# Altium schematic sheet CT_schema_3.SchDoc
size 176 x 147 mm
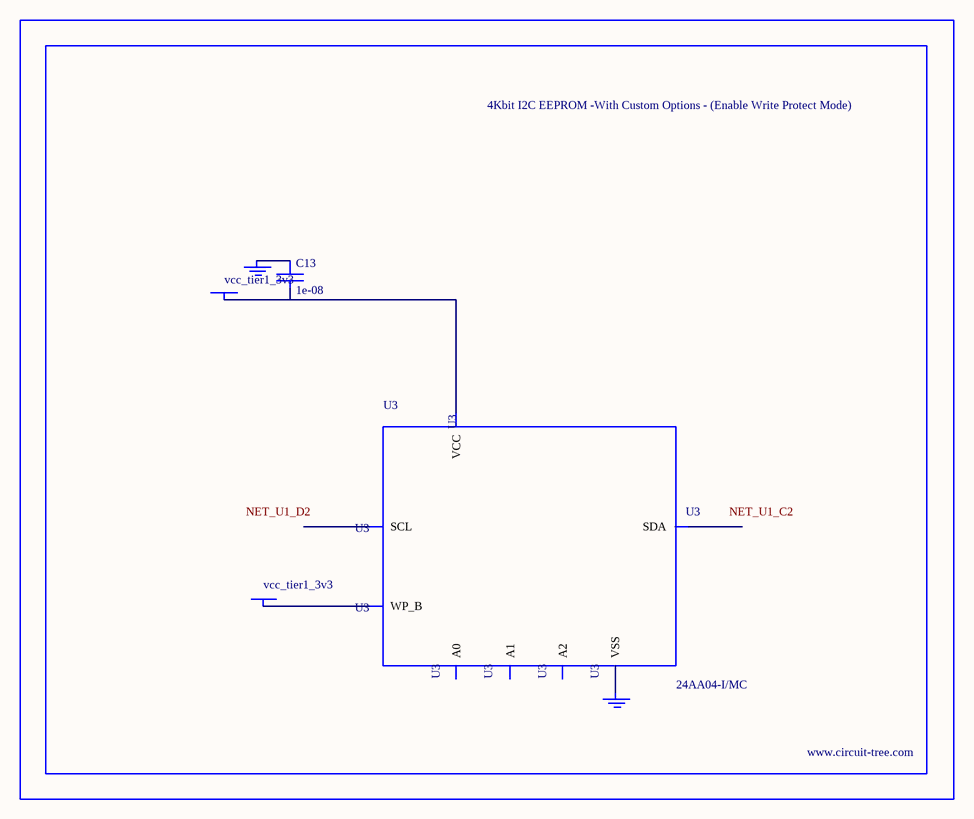
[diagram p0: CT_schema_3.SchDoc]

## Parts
BORDER2  (no value)
C13  1e-08  [C0402]
GND_INSTANCE_2_0  (no value)
GND_INSTANCE_2_1  (no value)
POWER_INSTANCE_2_0  vcc_tier1_3v3
POWER_INSTANCE_2_1  vcc_tier1_3v3
U3  24AA04-I/MC  [TDFN-8/6MM]

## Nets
NetC13_1: C13.1 GND_INSTANCE_2_0.0(GND)
NetC13_2: C13.2 POWER_INSTANCE_2_1.0(PWR) U3.8(VCC)
NetGND_INSTANCE_2_1_0: GND_INSTANCE_2_1.0(GND) U3.4(VSS)
NetPOWER_INSTANCE_2_0_0: POWER_INSTANCE_2_0.0(PWR) U3.7(WP_B)

Not connected (* = marked no-connect by the designer): U3 1(A0) 2(A1) 3(A2) 5(SDA) 6(SCL)

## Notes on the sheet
- Labels drawn without touching a wire or pin: NET_U1_C2, NET_U1_D2

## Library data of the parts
BORDER2 = BORDER_PAGE2
C13 = C0402C103K3RAC
GND_INSTANCE_2_0 GND_INSTANCE_2_1 = GND
POWER_INSTANCE_2_0 POWER_INSTANCE_2_1 = PWR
